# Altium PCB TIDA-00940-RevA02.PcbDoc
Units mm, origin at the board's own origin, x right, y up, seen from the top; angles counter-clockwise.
Board outline 125.73 x 87.63 mm, 2 copper layers (Top Layer, Bottom Layer), stack 1.575 mm thick; 42 components, 20 nets, 88 pads, 5 vias.
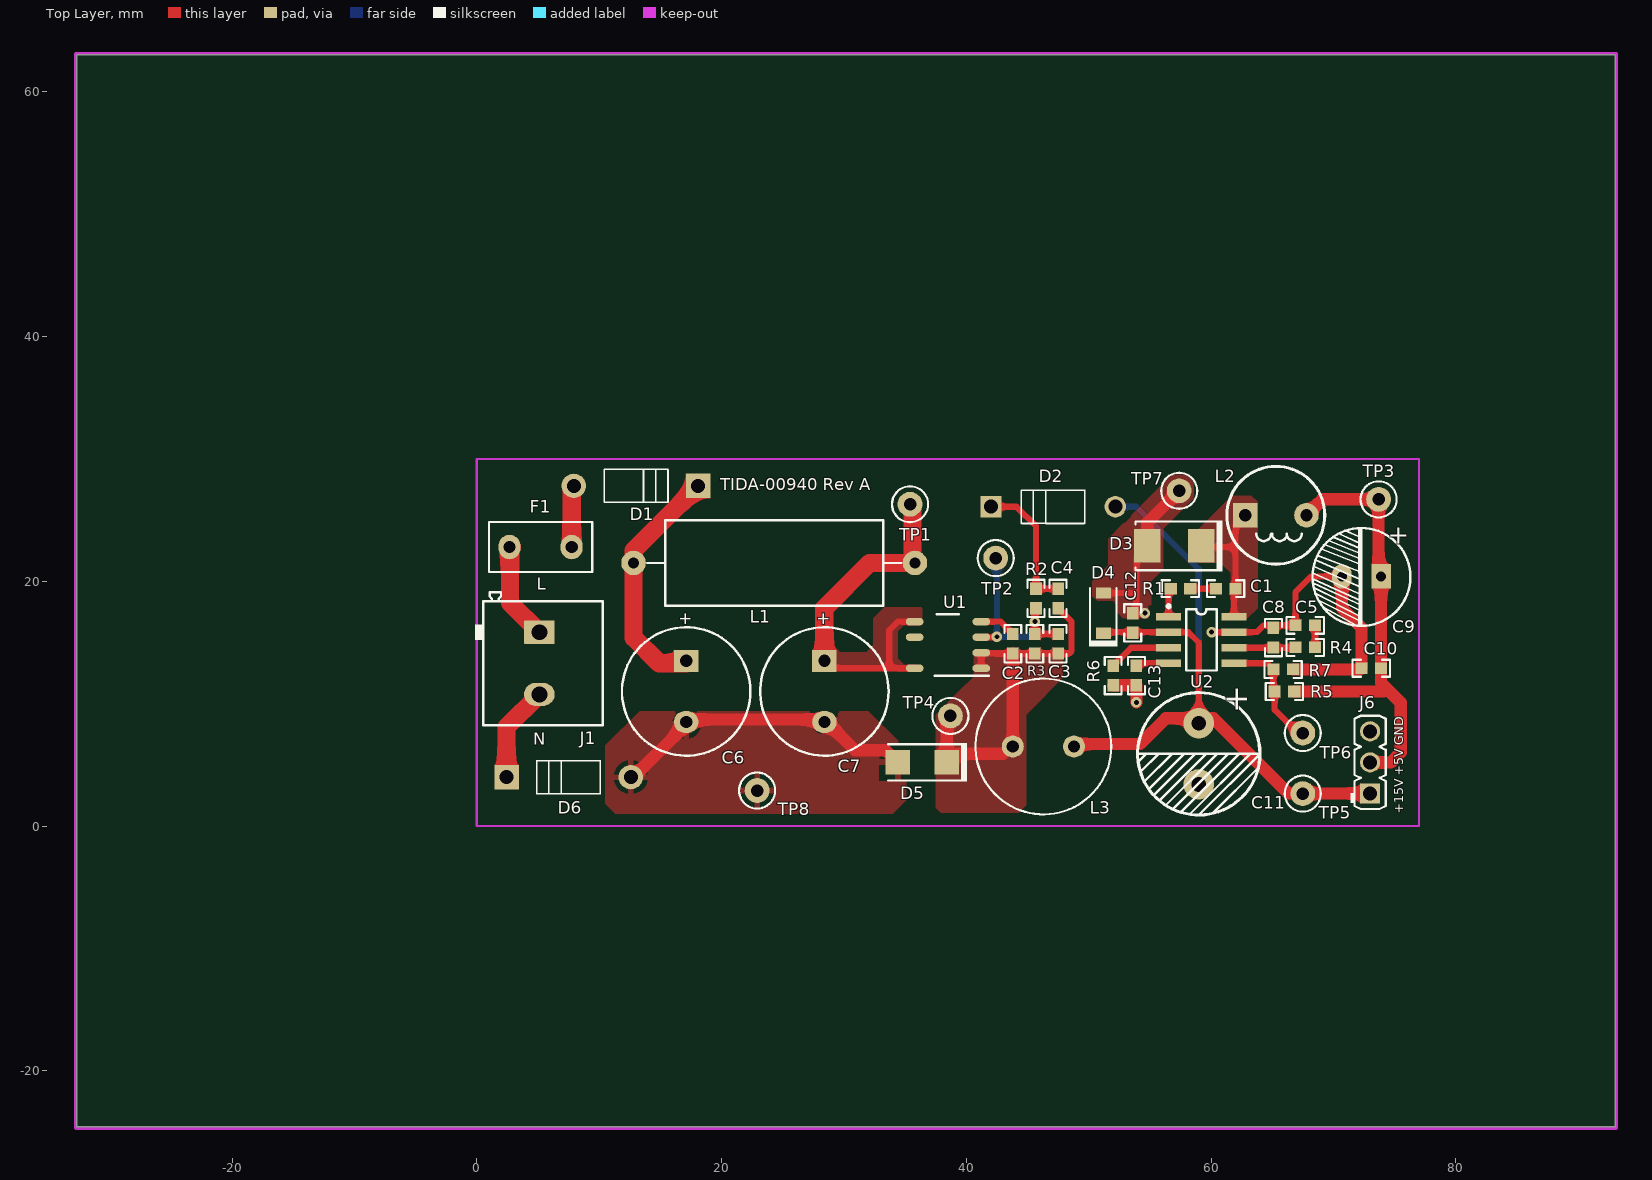
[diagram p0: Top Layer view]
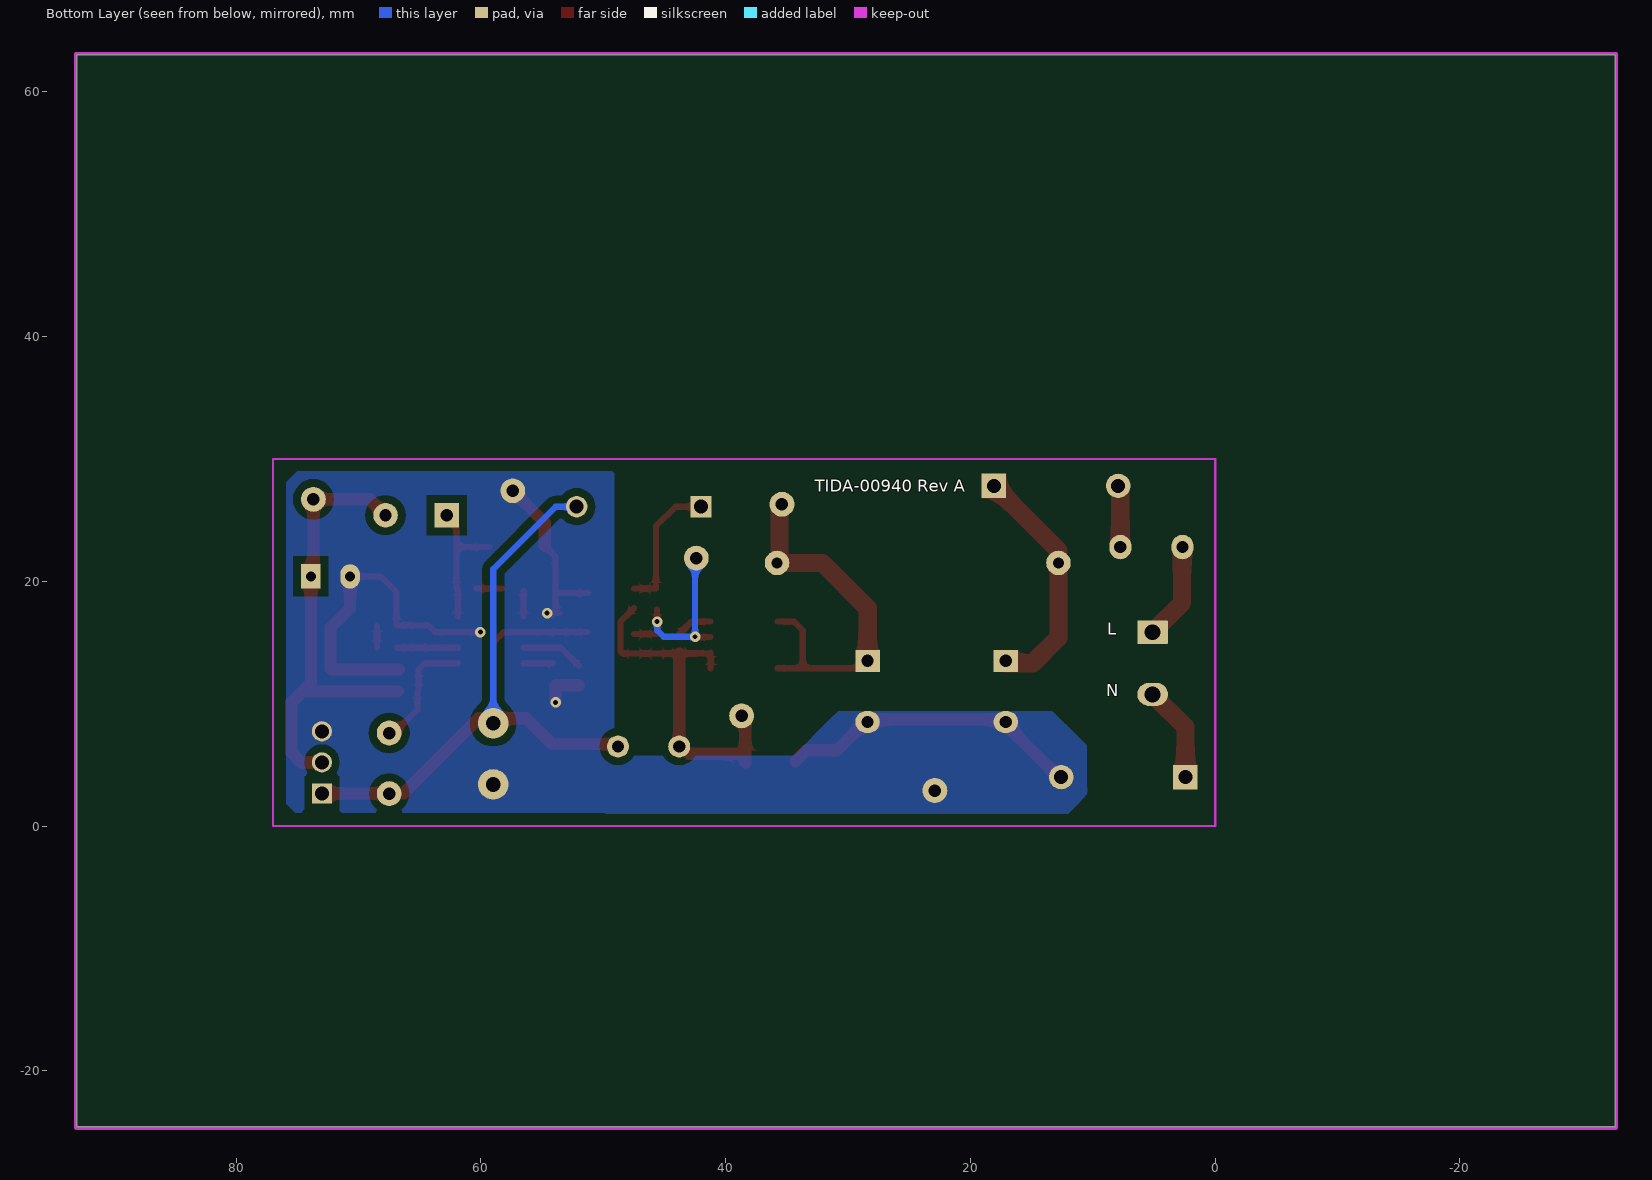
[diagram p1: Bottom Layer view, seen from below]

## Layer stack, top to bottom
Top Solder: solder mask 0.0102, Solder Resist, Dk 3.5
Top Layer: signal copper 0.0356
Dielectric1: core 1.5037, FR-4, Dk 4.8
Bottom Layer: signal copper 0.0356
Bottom Solder: solder mask 0.0102, Solder Resist, Dk 3.5

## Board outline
-32.7,-24.6 93.03,-24.6 93.03,63.03 -32.7,63.03

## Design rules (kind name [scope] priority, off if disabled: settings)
AcuteAngle [All] p1: minimum=4.50000000000000E+0001 checktracksonly=FALSE
AssemblyTestPointUsage [All] p1: valid=2
Clearance Clearance_Keepouts [((IsTrack Or IsArc) And Not InPoly) And IsFree and IsKeepOut vs ((IsTrack Or IsArc) And Not InPoly) And IsFree and IsKeepOut] p1 off: gap=0
Clearance Clearance_BoardEdge_MountingHoles [OnCopper and InComponentClass('Mounting Holes') vs IsKeepOut] p2 off: gap=1.016
Clearance Clearance_BoardEdge_Poly [OnCopper and InPoly vs IsKeepOut] p3 off: gap=0.635
Clearance Clearance_BoardEdge [OnCopper and Not InComponentClass('Logo') and not InComponentClass('FiducialMark') and not InRegion(1000,500,4000,800) and Not IsKeepout vs IsKeepOut] p4 off: gap=1.905
Clearance Clearance_Poly [InPolygon] p5: gap=0.635
Clearance [All] p6: gap=0.2
ComponentClearance ComponentClearance_MountingHoles_FiducialMarks [InComponentClass('Mounting Holes') vs InComponentClass('FiducialMark')] p1 off: gap=1.27 collisioncheckmode=3 verticalgap=0.254 showdistances=FALSE
ComponentClearance ComponentClearance_Shunt [InComponentClass('Header') vs InComponentClass('Shunt')] p2 off: gap=0 collisioncheckmode=3 verticalgap=0 showdistances=FALSE
ComponentClearance ComponentClearance_Logo [InComponentClass('Logo')] p3 off: gap=1.27 collisioncheckmode=3 verticalgap=0.254 showdistances=FALSE
ComponentClearance ComponentClearance_ScrewToNut [(HasFootprint('NY PMS 440 0025 PH')) vs (HasFootprint('Keystone_1902C'))] p4 off: gap=0.127 collisioncheckmode=3 verticalgap=0.254 showdistances=FALSE
ComponentClearance ComponentClearance_MountingHoles [InComponentClass('Mounting Holes')] p5 off: gap=6.35 collisioncheckmode=3 verticalgap=2540 showdistances=FALSE
ComponentClearance ComponentClearance_SmallPassives [HasFootprint('0201*') or HasFootprint('0402*') or HasFootprint('0508') or HasFootprint('0603*') or HasFootprint('0612') or HasFootprint('0805*') or HasFootprint('0815*') or HasFootprint('0830*') or HasFootprint('1206*') or HasFootprint('1210*') or HasFootprint('1808*') or HasFootprint('1812*') or HasFootprint('1825*') or HasFootprint('2010*') or HasFootprint('2220*') or HasFootprint('2225*') or HasFootprint('2512*') or HasFootprint('2728*') or HasFootprint('3518*') vs HasFootprint('0201*') or HasFootprint('0402*') or HasFootprint('0508') or HasFootprint('0603*') or HasFootprint('0612') or HasFootprint('0805*') or HasFootprint('0815*') or HasFootprint('0830*') or HasFootprint('1206*') or HasFootprint('1210*') or HasFootprint('1808*') or HasFootprint('1812*') or HasFootprint('1825*') or HasFootprint('2010*') or HasFootprint('2220*') or HasFootprint('2225*') or HasFootprint('2512*') or HasFootprint('2728*') or HasFootprint('3518*')] p6 off: gap=0.508 collisioncheckmode=3 verticalgap=0.254 showdistances=FALSE
ComponentClearance ComponentClearance_THtoSMT [IsThruComponent vs IsSMTComponent] p7 off: gap=2.54 collisioncheckmode=3 verticalgap=0.762 showdistances=FALSE
ComponentClearance ComponentClearance_THtoTH [IsThruComponent vs IsThruComponent] p8 off: gap=3 collisioncheckmode=3 verticalgap=0.762 showdistances=FALSE
ComponentClearance [All] p9 off: gap=1.016 collisioncheckmode=3 verticalgap=0.254 showdistances=FALSE
DiffPairsRouting [All] p1: maxlimit=2.54 minlimit=0.254 mostfreqgap=0.254 toplayer_minwidth=0.381 toplayer_maxwidth=0.381 toplayer_prefwidth=0.381 bottomlayer_minwidth=0.381 bottomlayer_maxwidth=0.381 bottomlayer_prefwidth=0.381 maxuncoupledlength=25.4
FabricationTestPointUsage TestPointUsage [All] p1: valid=2 allowmultiple=FALSE
FabricationTestpoint Testpoint [All] p1: side=3 testpointundercomponent=TRUE minsize=1.016 maxsize=2.54 preferedsize=1.524 minholesize=0 maxholesize=1.016 preferedholesize=0.813 testpointgrid=0.025 allowsidetop=TRUE allowsidebottom=TRUE usegrid=TRUE gridtolerance=0
FanoutControl Fanout_LCC [IsLCC] p1: bgadir=Out bgaviamode=Centered fanoutstyle=Auto fanoutdirection=Alternating viagrid=0.025 // Fanout_LCC (Default Rule)
FanoutControl Fanout_BGA [IsBGA] p2: bgadir=Out bgaviamode=Centered fanoutstyle=Auto fanoutdirection=Alternating viagrid=0.025 // Fanout_BGA (Default Rule)
FanoutControl Fanout_Default [All] p4: bgadir=Out bgaviamode=Centered fanoutstyle=Auto fanoutdirection=Alternating viagrid=0.025 // Fanout_Default (Default Rule)
FanoutControl Fanout_Small [(CompPinCount < 5)] p5: bgadir=Out bgaviamode=Centered fanoutstyle=Auto fanoutdirection=OutThenIn viagrid=0.025 // Fanout_Small (Default Rule)
HoleSize [All] p1: absolutevalues=TRUE maxlimit=6.375 minlimit=0.203 maxpercent=80.000 minpercent=20.000
MinimumAnnularRing MinimumAnnularRing_ThermalPadVias [IsVia and InAnyComponent] p1: minimumring=0.15
MinimumAnnularRing [All] p2: minimumring=0.229
MinimumSolderMaskSliver MinimumSolderMaskSliver_Logo [InComponentClass('Logo') vs InComponentClass('Logo')] p1: minsoldermaskwidth=0.018
MinimumSolderMaskSliver [All] p2: minsoldermaskwidth=0.1
PlaneConnect [All] p1: planeconnectstyle=Relief reliefexpansion=0.254 reliefentries=4 reliefconductorwidth=0.254 reliefairgap=0.254
PolygonConnect [All] p1: connectstyle=Direct reliefconductorwidth=0.5 reliefentries=4 polygonreliefangle="90 Angle" airgapwidth=0.5
RoomDefinition TIDA-00940-RevA01 [InComponentClass('TIDA-00940-RevA01')] p1: confinementstyle=ConfineIn formatcopy=TRUE lockcomponents=FALSE outline -50.277,-63.564 0.523,-63.564 0.523,-38.164 -50.277,-38.164
RoutingVias ThermalPadVias [IsVia and InAnyComponent] p1: holewidth=0.2 width=0.5 viastyle="Through Hole" minholewidth=0.2 minwidth=0.5 maxholewidth=0.33 maxwidth=0.6
RoutingVias [All] p2: holewidth=0.406 width=0.864 viastyle="Through Hole" minholewidth=0.2 minwidth=0.66 maxholewidth=1.016 maxwidth=1.651
SilkToBoardRegionClearance [Not ((IsComment or IsDesignator) And (Hide <> 'False')) and not InRegion(1000,500,4000,800)] p1:
SilkToSilkClearance SilkToSilkClearance_Pb-FreeLogo [(HasFootprint('Pb-Free_Overlay_Medium') OR HasFootprint('Pb-Free_Overlay_Small')) vs (HasFootprint('Pb-Free_Overlay_Medium') OR HasFootprint('Pb-Free_Overlay_Small'))] p1: silktosilkclearance=0
SilkToSilkClearance [All] p2: silktosilkclearance=0.102
SilkToSolderMaskClearance SilkToComonentPadClearance [IsPad and InAnycomponent] p1: minsilkscreentomaskgap=0.127 clearancetoexposedcopper=TRUE
SilkToSolderMaskClearance "Silk to Solder Mask Opening" [All] p2: minsilkscreentomaskgap=0.102 clearancetoexposedcopper=FALSE
SolderMaskExpansion [All] p1: expansion=0.05
UnpouredPolygon [All] p1: allowunpoured=FALSE
Width [All] p1: maxlimit=2.54 minlimit=0.152 preferedwidth=0.254 checkconnectedcopper=TRUE
14 further rules are at their usual default settings.

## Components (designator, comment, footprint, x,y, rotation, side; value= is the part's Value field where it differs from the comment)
C1 "C1608X7R1H104K080AA" 0603 61.2,19.4 r0 top
C2 "C1608X7R1H104K080AA" 0603 43.8,14.9 r270 top
C3 "C1608X7R1H103K" 0603 47.5,14.9 r270 top
C4 "C1608X7R1H153K080AA" 0603 47.5,18.6 r270 top
C5 "06031C222JAT2A" 0603 67.7,16.4 r0 top
C6 "UCY2G100MPD1TD" CY_1000x1600 17.1,11 r270 top
C7 "UCY2G100MPD1TD" CY_1000x1600 28.4,11 r270 top
C8 "06035A101FAT2A" 0603 65.1,15.4 r270 top
C9 "UPW1A471MPD" E/P3.2/D8 72.3,20.4 r180 top
C10 "C1608X7R1H103K" 0603 73.1,12.9 r180 top
C11 "UPW1E331MPD" E5/10 59,5.9 r270 top
C12 "C1608X7R1H103K" 0603 53.6,16.6 r90 top
C13 "C1608X7R1H103K" 0603 53.9,12.3 r270 top
D1 "1N4007" DO-41#1 13,27.8 r180 top
D2 "1N4007" DO-41#2 47.1,26.1 r0 top
D3 "B240-13-F" SMB 57,22.9 r180 top
D4 "MMSZ4705T1G" SOD-123 51.2,17.4 r90 top
D5 "US1M-13-F" SMA 36.4,5.2 r180 top
D6 "1N4007" DO-41#1 7.5,4 r0 top
F1 "RST 500" Fuse_RST 5.2,22.8 r180 top
J1 "1715721" PhoenixContact_1715721 5.1,13.3 r270 top
J6 "61300311121" WURTH_61300311121 73,5.2 r90 top
L1 "5800-102-RC" 5800 24.3,21.5 r0 top
L2 "7447471102" Inductor-P5D8 65.3,25.4 r90 top
L3 "7447471102" WE-TIS-1111 46.3,6.5 r0 top
R1 "CRCW06030000Z0EA" 0603 57.5,19.4 r0 top
R2 "RT0603DRE07135KL" 0603 45.7,18.6 r90 top
R3 "RC0603FR-0710KL" 0603 45.6,14.9 r90 top
R4 "CRCW060347K0JNEA" 0603 67.7,14.6 r0 top
R5 "RC0603FR-0751RL" 0603 66,11 r0 top
R6 "CRCW0603100KFKEA" 0603 52,12.3 r90 top
R7 "CRCW06033K90JNEA" 0603 65.9,12.8 r180 top
TP1 "5000" Keystone5000 35.4,26.3 r0 top
TP2 "5000" Keystone5000 42.4,21.9 r0 top
TP3 "5000" Keystone5000 73.7,26.7 r0 top
TP4 "5000" Keystone5000 38.7,9 r0 top
TP5 "5000" Keystone5000 67.501,2.647 r0 top
TP6 "5000" Keystone5000 67.5,7.6 r0 top
TP7 "5001" Keystone5001 57.4,27.4 r0 top
TP8 "5001" Keystone5001 22.9,2.9 r0 top
U1 "UCC28881DR" D0007A_N 38.5,14.8 r180 top
U2 "TPS5405" SO-G8/E2.5 59.2,15.2 r270 top

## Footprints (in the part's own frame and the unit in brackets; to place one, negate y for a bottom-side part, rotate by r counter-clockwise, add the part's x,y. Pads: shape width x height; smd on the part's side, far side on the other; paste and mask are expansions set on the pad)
0603 [mm] "0603 from SM-752 data"
  rect 1x0.95 smd: 1(-0.8,0) 2(0.8,0)
  silkscreen extent -1.52,-0.69 1.52,0.69, body extent -0.87,-0.47 0.87,0.47, height 1
5800 [mm] "BOURNS"
  round 2 hole 0.9: 1(-11.5,0) 2(11.5,0)
  silkscreen extent -10.4,-3.5 10.4,3.5, body extent -11.81,-3.5 11.82,3.48, height 6.96
CY_1000x1600 [mm] "TH, 2-Leads, Dia 10mm, Pitch 5mm"
  rect 1.8x2 hole 1: 1(-2.5,0)
  oval 1.8x2 hole 1: 2(2.5,0)
  silkscreen extent -5.25,-5.25 5.25,5.25, body extent -5.2,-5.23 5.25,5.25, height 17.5
D0007A_N [mm] "SOIC, 7-Leads, Body 4.9x3.9mm, Pitch 1.27mm, IPC Medium Density"
  oval 1.45x0.6 smd: 1(-2.725,1.905) 2(-2.725,0.635) 3(-2.725,-0.635) 4(-2.725,-1.905) 5(2.725,-1.905) 6(2.725,-0.635) 8(2.725,1.905)
  silkscreen extent -3.32,-2.5 1.1,2.52, body extent -3.01,-2.45 3.01,2.45, height 1.75
DO-41#1 [mm] "diode"
  rect 2x2 hole 1.15: 1(-5.08,0)
  round 2 hole 1.15: 2(5.08,0)
  silkscreen extent -2.62,-1.37 2.59,1.35, body extent -5.51,-1.36 5.51,1.36, height 2.72
DO-41#2 [mm] "diode"
  rect 1.75x1.75 hole 1.15: 1(-5.08,0)
  round 1.75 hole 1.15: 2(5.08,0)
  silkscreen extent -2.62,-1.37 2.59,1.35, body extent -5.51,-1.36 5.51,1.36, height 2.72
E5/10 [mm]
  round 2.5 hole 1.2: 1(-2.5,0) 2(2.5,0)
  silkscreen extent -5,-5 5,5
E/P3.2/D8 [mm]
  rect 1.6x2 hole 0.8: 1(-1.6,0)
  oval 1.6x2 hole 0.8: 2(1.6,0)
  silkscreen extent -4,-3.96 4,4.04
Fuse_RST [mm] "Bel Fuse RST series May2012D"
  oval 1.8x2 hole 1: 1(-2.54,0) 2(2.54,0)
  silkscreen extent -4.23,-2.05 4.23,2.05, body extent -4.22,-2.05 4.23,2.05, height 7.9
Inductor-P5D8 [mm]
  rect 2x2 hole 1: 1(0,2.5)
  round 2 hole 1: 2(0,-2.5)
  silkscreen extent -4,-4 4,4
Keystone5000 [mil] "For Keystone 500x miniature loop terminals"
  round 80 hole 40: 1(0,0)
  silkscreen extent -58,-58 58,58, body extent -49,-49 49,49, height 182
Keystone5001 [mil] "For Keystone 500x miniature loop terminals"
  round 80 hole 40: 1(0,0)
  silkscreen extent -58,-58 58,58, body extent -49,-49 49,49, height 182
PhoenixContact_1715721 [mm] "Phoenix Contact 1715721 used on LM3445 design from Longmont"
  rrect5% 1.9x2.5 hole 1.3: 1(-2.54,0)
  oval 1.9x2.5 hole 1.3: 2(2.54,0)
  silkscreen extent -5.82,-5.25 5.08,5.2, body extent -5.82,-4.6 5.08,5.2, height 14.2
SMA [mm] "Molded Diode, 2-Leads, Body 4.3x2.6mm, IPC Medium Density, based on OnSemi component dimensions and land pattern"
  rect 2x2 smd: 1(-2,0) 2(2,0)
  silkscreen extent -3.66,-1.57 2.79,1.57, body extent -2.6,-1.3 2.6,1.3, height 2.42
SMB [mm] "Molded Diode, 2-Leads, Body 5.4x3.6mm, IPC Medium Density, based on OnSemi component dimensions"
  rect 2.159x2.743 smd: 1(-2.21,0) 2(2.21,0)
  silkscreen extent -3.94,-2.08 3.18,2.08, body extent -2.7,-1.8 2.7,1.8, height 2.32
SO-G8/E2.5 [mm]
  rect 0.6x2.05 smd: 1(-1.915,-2.666) 2(-0.645,-2.666) 3(0.625,-2.666) 4(1.895,-2.666) 5(1.895,2.684) 6(0.625,2.684) 7(-0.645,2.684) 8(-1.915,2.684)
  silkscreen extent -2.89,-2.79 2.49,1.26
SOD-123 [mm] "On Semi recommended land pattern"
  rect 0.915x1.22 smd: 1(-1.637,0) 2(1.637,0)
  silkscreen extent -2.74,-1.17 2.03,1.17, body extent -1.93,-0.9 1.93,0.9, height 1.35
WE-TIS-1111 [mm] "WURTH"
  round 1.8 hole 1.016: 1(-2.5,0) 2(2.5,0)
  silkscreen extent -5.55,-5.55 5.55,5.55, body extent -5.51,-5.51 5.51,5.51, height 11.5
WURTH_61300311121 [mm] "Header, 2.54mm, 3x1, TH"
  rect 1.65x1.65 hole 1.15: 1(-2.54,0)
  round 1.65 hole 1.15: 2(0,0) 3(2.54,0)
  silkscreen extent -3.81,-1.27 3.81,1.6, body extent -3.81,-1.27 3.81,1.27, height 8.54

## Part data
C1 C2: "CAP, CERM, 0.1 µF, 50 V, +/- 10%, X7R, 0603"
C3 C10 C12 C13: "CAP, CERM, 0.01 µF, 50 V, +/- 10%, X7R, 0603"
C4: "CAP, CERM, 0.015 µF, 50 V, +/- 10%, X7R, AEC-Q200 Grade 1, 0603"
C5: "CAP, CERM, 2200 pF, 100 V, +/- 5%, X7R, 0603"
C6 C7: "CAP, AL, 10 µF, 400 V, +/- 20%,  ohm, TH"
C8: "CAP, CERM, 100 pF, 50 V, +/- 1%, C0G/NP0, 0603"
C9: library part UVR1V100MDD1TA, "CAP, AL, 10 µF, 35 V, +/- 20%, TH"
C11: library part UVR1V100MDD1TA, "CAP, AL, 330 µF, 25 V, +/- 20%, TH"
D1 D2 D6: "Diode, P-N, 1000 V, 1 A, TH"
D3: "Diode, Schottky, 40 V, 2 A, SMB"
D4: "Diode, Zener, 18 V, 500 mW, SOD-123"
D5: "Diode, Ultrafast, 1000 V, 1 A, SMA"
F1: "Fuse, 0.5 A, 250VAC/VDC, TH"
J1: "Conn Term Block, 2POS, 5.08mm, TH"
J6: "Header, 2.54 mm, 3x1, Gold, TH"
L1: "Inductor, Wirewound, Ferrite, 1 mH, 0.2 A, 2.3 ohm, TH"
L2: "Inductor, Wirewound, Ferrite, 82uH, 1.1 A, 1.2 ohm, TH"
L3: "Inductor, Wirewound, Ferrite, 1 mH, 0.4 A, 1.2 ohm, TH"
R1: "RES, 0, 5%, 0.1 W, 0603"
R2: "RES, 135 k, 0.5%, 0.1 W, 0603"
R3: "RES, 10.0 k, 1%, 0.1 W, 0603"
R4: "RES, 47 k, 5%, 0.1 W, 0603"
R5: "RES, 51.0, 1%, 0.1 W, 0603"
R6: "RES, 100 k, 1%, 0.1 W, 0603"
R7: "RES, 3.9 k, 5%, 0.1 W, 0603"
TP1 TP2 TP3 TP4 TP5 TP6: "Test Point, Miniature, Red, TH"
TP7 TP8: "Test Point, Miniature, Black, TH"
U1: "700-V Lowest Quiescent Current Off-Line Switcher, D0007A"

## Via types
v1: diameter 0.864, hole 0.406, Top Layer to Bottom Layer, 5 vias

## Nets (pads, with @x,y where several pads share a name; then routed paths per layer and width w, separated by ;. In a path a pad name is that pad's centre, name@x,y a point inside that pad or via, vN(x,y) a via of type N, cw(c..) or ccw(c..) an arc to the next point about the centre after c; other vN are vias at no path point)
+5V: C9.1 C10.1 J6.2 L2.2 R5.2 TP3.1 | length 37.8
  Top Layer w1: R5.2 74.1,11 74.35,11.25 ; L2.2 69.1,26.7 TP3.1 C9.1@73.7,20.6 ; J6.2 74.7,5.2 75.5,6 75.5,10.1 74.35,11.25 ; C10.1 73.9,11.7 74.35,11.25 ; C10.1@73.9,13.2 C9.1
+15V: C11.1 C12.1 D2.2 D4.1 J6.1 L3.2 TP5.1 U2.2 | length 63.4
  Top Layer w0.5: D4.1@51.282,15.845 U2.2 58.155,15.845 59,15 C11.1@59,8.8
  Top Layer w1: L3.2@48.8,6.7 54.2,6.7 56.3,8.8 59,8.8 60.2,8.8 66.34,2.66 J6.1
  Bottom Layer w0.5: D2.2 53.9,26.1 59,21 C11.1
GND: C5.1 C6.2 C7.2 C8.1 C9.2 C10.2 C11.2 C12.2 C13.2 D3.2 D4.2 D5.2 D6.2 J6.3 R6.1 R7.1 TP7.1 TP8.1 U2.7 | length 70.6
  Top Layer w0.5: D4.2 53.862,19.038 53.9,19 ; C12.2 v1(54.6,17.4) ; C12.2@53.9,17.4 53.9,19 ; D3.2 53.9,22.01 53.9,19 ; v1(60.045,15.855) 60.045,15.845 U2.7 63.745,15.845 64.3,16.4 C5.1 66.9,19.1 68.2,20.4 C9.2
  Top Layer w1: D6.2@12.8,4 C6.2@17.1,8.3 ; C6.2@17.5,8.7 28.4,8.7 30.9,6.2 33.4,6.2 D5.2@34.3,5.3 ; R6.1 C13.2 v1(53.9,10.1) ; D3.2 54.79,24.79 TP7.1 ; R7.1 C10.2@72.2,12.8 ; C9.2 70.7,17.8 72.3,16.2 C10.2
NetC1_1: C1.1 R1.2 | length 2.1
  Top Layer w0.5: R1.2 C1.1
NetC1_2: C1.2 D3.1 L2.1 U2.8 | length 11.2
  Top Layer w0.5: D3.1@59.31,22.8 62,22.8 ; U2.8 C1.2@61.884,19.284 ; C1.2 62,22.8 ; L2.1 62,24.6 62,22.8
NetC2_1: C2.1 U1.4 | length 3
  Top Layer w0.5: U1.4 42.795,16.705 C2.1
NetC2_2: C2.2 C3.2 C4.2 D5.1 L3.1 R3.1 TP4.1 U1.1 U1.2 | length 29
  Top Layer w0.5: U1.1 U1.2 ; U1.2@41.29,14.1 R3.1 C3.2 48.4,14.1 48.6,14.3 48.6,16.7 C4.2
  Top Layer w1: D5.1 TP4.1@38.4,8.7 ; D5.1@38.75,5.75 38.9,5.9 43,5.9 43.8,6.7 C2.2
NetC3_1: C3.1 R2.1 R3.2 TP2.1 U1.3 | length 15.5
  Top Layer w0.5: U1.3 42.465,15.435 v1(42.5,15.47) ; R2.1@45.6,17.7 v1(45.6,16.7) R3.2 C3.1
  Bottom Layer w0.5: TP2.1@42.5,21.8 v1(42.5,15.47) 45.07,15.47 45.6,16 v1(45.6,16.7)
NetC4_1: C4.1 D2.1 R2.2 | length 11.2
  Top Layer w0.5: D2.1 44.1,26.1 45.7,24.5 R2.2 C4.1
NetC5_2: C5.2 R4.2 | length 1.8
  Top Layer w0.5: R4.2 C5.2
NetC6_1: C6.1 D1.1 L1.1 | length 19.7
  Top Layer w1: L1.1@12.7,21.4 L1.1@12.8,21.3
  Top Layer w1.5: L1.1@12.8,21.3 12.8,15.4 14.9,13.3 C6.1@17.1,13.3 ; L1.1 12.8,22.52 D1.1
NetC7_1: C7.1 L1.2 TP1.1 U1.5 U1.8 | length 30.6
  Top Layer w0.5: C7.1@28.4,13.7 29.205,12.895 33.7,12.895 ; U1.8 33.7,12.895 ; U1.5 34.405,16.705 33.7,16 33.7,12.895
  Top Layer w1.5: C7.1@28.4,13.7 28.4,17.8 32.1,21.5 35.6,21.5 TP1.1@35.6,26.1
NetC8_2: C8.2 R4.1 U2.6 | length 5
  Top Layer w0.5: U2.6 R4.1@66.875,14.575
NetC13_1: C13.1 U2.4 | length 2.4
  Top Layer w0.5: C13.1@54.105,13.305 U2.4
NetD1_2: D1.2 F1.1 | length 4.7
  Top Layer w1.5: F1.1 D1.2@7.74,27.48
NetD6_1: D6.1 J1.2 | length 7.9
  Top Layer w1.5: D6.1 2.42,8.08 J1.2
NetF1_2: F1.2 J1.1 | length 8
  Top Layer w1.5: F1.2@2.86,22.8 2.7,22.64 2.7,18.24 J1.1
NetR1_1: R1.1 U2.1 | length 2.1
  Top Layer w0.5: U2.1 R1.1@56.534,19.234
NetR5_1: R5.1 R7.2 TP6.1 U2.5 | length 9.3
  Top Layer w0.5: U2.5 64.595,13.305 R7.2 R5.1@65.1,11.1 ; R5.1 65.2,9.5 TP6.1@67.1,7.6
NetR6_2: R6.2 U2.3 | length 5.1
  Top Layer w0.5: R6.2 53.475,14.575 U2.3
pads on no net: U1.6

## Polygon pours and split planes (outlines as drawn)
GND on Top Layer "Top Layer-No Net" (solid, remove dead copper, pour order 2): 35.1,6.3 32,9.4 24.8,9.4 13.3,9.4 10.5,6.6 10.5,1.8 11.3,1 15.3,1 34,1 35.1,2.1
NetC7_1 on Top Layer "Top Layer-No Net 2" (solid, remove dead copper, pour order 8): 28.9,14.9 29,14.9 29.7,14.2 31.8,14.2 32.4,14.8 32.4,16.1 32.4,17 32.8,17.4 33.3,17.9 35.7,17.9 36.3,17.9 36.4,17.8 36.4,16.7 36.4,16.5 36.3,16.4 34.9,16.4 34.4,15.9 34.4,13.7 34.8,13.3 34.9,13.2 35.9,13.2 36,13.2 36.1,13.1 36.2,13 36.2,12.6 34.4,12.6 34.3,12.7 29.1,12.7
NetC1_2 on Top Layer "Top Layer-No Net 3" (solid, remove dead copper, pour order 10): 58.7,24 61.7,27 63.3,27 63.8,26.5 63.8,24.9 63.8,17.8 62.9,16.9 62.8,17 61.6,17 61.6,20.7 61.1,21.2 60.8,21.5 59,21.5
NetC2_2 on Top Layer "Top Layer-No Net 4" (solid, remove dead copper, pour order 12): 41.2,14.378 47.822,14.378 47.9,14.3 47.9,12.1 45.2,9.4 44.9,9.1 44.9,6.7 44.9,1.7 44.3,1.1 37.9,1.1 37.5,1.5 37.5,9.1 39.4,11 40.6,12.2 40.6,14.3
GND on Top Layer "Top Layer-No Net 5" (solid, remove dead copper, pour order 14): 54.6,17 52.8,17 52.4,17.4 52.3,17.5 52.3,18.1 52,18.4 50.7,18.4 50.3,18.8 50.3,18.9 50.3,20 50.8,20.5 51.6,21.3 51.6,23.5 56.8,28.7 58,28.7 58.6,28.1 58.6,27.2 58.6,26.8 56.9,25.1 56.1,24.3 56.1,21.8 56.1,21 55.3,20.2 55.1,20 55.1,17.6 55.1,17.2 54.9,17
GND on Bottom Layer "Top Layer-No Net 1" (solid, remove dead copper, pour order 4): 49.1,29 49.1,1.7 49.7,1.1 75.2,1.1 75.9,1.8 75.9,28.1 75,29
GND on Bottom Layer "Bottom Layer-No Net" (solid, remove dead copper, pour order 6): 40.75,5.75 38.75,5.75 34.45,5.75 31.4,8.8 30.8,9.4 23.1,9.4 13.3,9.4 11.2,7.3 10.5,6.6 10.5,4.693 10.496,3.455 10.464,2.877 10.504,2.592 11.2,1.8 12,1 49.8,1 50.1,1.3 50.1,5.75

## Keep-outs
Keep-Out Layer:
  lines w0.2: 0,0 0,30 77,30 77,0 0,0
  lines w0.254: -32.827,-24.6 ccw(c-32.7,-24.6) -32.7,-24.727 ; -32.827,-24.6 ccw(c-32.7,-24.6) -32.7,-24.727 ; -32.827,-24.6 -32.827,63.03 ; -32.827,63.03 cw(c-32.7,63.03) -32.7,63.157 ; -32.827,63.03 cw(c-32.7,63.03) -32.7,63.157 ; -32.7,-24.727 93.03,-24.727 ; -32.7,63.157 93.03,63.157 ; 93.03,-24.727 ccw(c93.03,-24.6) 93.157,-24.6 ; 93.03,-24.727 ccw(c93.03,-24.6) 93.157,-24.6 ; 93.03,63.157 cw(c93.03,63.03) 93.157,63.03 ; 93.03,63.157 cw(c93.03,63.03) 93.157,63.03 ; 93.157,-24.6 93.157,63.03
  text ".Layer_Name" at -18.044,-46.406 h1.52

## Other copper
Top Layer:
  text ".Layer_Name" at -18.044,-46.406 h1.52
Bottom Layer:
  text ".Layer_Name" at -18.044,-46.406 h1.52

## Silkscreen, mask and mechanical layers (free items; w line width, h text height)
Top Overlay:
  text "TIDA-00940 Rev A" at 19.9,27.1 h1.7
  text "L" at 4.9,19 h1.7
  text "GND" at 76,6.6 h1.3 r90
  text "N" at 4.6,6.3 h1.7
  text "+5V" at 76,4.1 h1.3 r90
  text "+15V" at 76,1 h1.3 r90
  text ".Layer_Name" at -18.044,-46.406 h1.52
Bottom Overlay:
  text "TIDA-00940 Rev A" at 32.7,27 h1.7
  text "L" at 8.8,15.3 h1.7
  text "N" at 8.9,10.3 h1.7
  text ".Layer_Name" at -18.044,-46.406 h1.52
Top Paste:
  text ".Layer_Name" at -18.044,-46.406 h1.52
Bottom Paste:
  text ".Layer_Name" at -18.044,-46.406 h1.52
Top Solder:
  text ".Layer_Name" at -18.044,-46.406 h1.52
  text ".Layer_Name" at -18.044,-46.406 h1.52
Bottom Solder:
  text ".Layer_Name" at -18.044,-46.406 h1.52
Drill Guide:
  text ".Layer_Name" at -18.044,-46.406 h1.52
M1 Board Outline:
  lines w0.254: -32.7,-24.6 -32.7,63.03 93.03,63.03 93.03,-24.6 -32.7,-24.6
  lines w3: 1.9,13.3 7.8,13.3 ; 10.2,19.6 10.2,25.5 ; 15.4,11 35.3,11 37,11 38.5,12.5 38.5,13.9 ; 38.5,13.6 38.5,27.8
  text ".Layer_Name" at -18.044,-46.406 h1.52
M2 Board Dimensions:
  rectangle: -32.7,-31.585 -29.525,-28.41
  rectangle: -29.525,-34.76 -20,-31.585
  lines w0.178: -32.7,-31.585 -7.3,-31.585 ; -29.525,-34.76 -29.525,-28.41 ; -26.35,-34.76 -26.35,-28.41 ; -20,-34.76 -20,-28.41 ; -13.65,-34.76 -13.65,-28.41 ; -32.7,-34.76 -7.3,-34.76 -7.3,-28.41 -32.7,-28.41 -32.7,-34.76
  text ".Layer_Name" at -18.044,-46.406 h1.52
M3 3D STEP Top:
  text ".Layer_Name" at -18.044,-46.406 h1.52
M4 3D STEP Bottom:
  text ".Layer_Name" at -18.044,-46.406 h1.52
M5 Assembly Top:
  lines w0.254: -40.117,-48.226 127.523,-48.226 ; -40.117,-43.062 127.574,-43.062 ; -40.117,-37.897 -40.117,-53.391 61.61,-53.391 127.574,-53.391 127.574,-37.897 -40.104,-37.897 -40.104,-53.391 -0.086,-53.391 ; 22.494,-53.391 22.494,-37.897 ; 54.676,-43.062 54.676,-37.897 ; 76.012,-43.062 76.012,-37.897 ; 91.811,-53.556 91.811,-48.404
  text "COMPONENTS MARKED 'DNP' SHOULD NOT BE POPULATED." at -3.401,-32.69 h1.52
  text "ASSEMBLY VARIANT:" at -3.414,-35.624 h1.52
  text ".VariantName" at 22.901,-35.624 h1.52
  text "PCB VIEWED FROM TOP SIDE" at -38.504,-41.254 h1.52
  text "BOARD #:" at 24.399,-41.254 h1.52
  text ".PRJ_Number" at 38.255,-41.254 h1.52
  text "REV:" at 59.705,-41.254 h1.52
  text ".PCB_Rev" at 67.109,-41.254 h1.52
  text "SVN REV:" at 80.99,-41.254 h1.52
  text ".VersionControl_RevNumber" at 93.843,-41.254 h1.52
  text "TID #:" at 24.399,-46.419 h1.52
  text ".TID" at 38.255,-46.419 h1.52
  text "PLOT NAME =" at -38.504,-51.634 h1.52
  text ".plot_File_Name" at -18.044,-51.634 h1.52
  text "GENERATED    :" at 24.45,-51.634 h1.52
  text ".Print_Date" at 46.535,-51.634 h1.52
  text ".Print_Time" at 65.052,-51.634 h1.52
  text "TEXAS INSTRUMENTS" at 97.17,-51.634 h1.52
M6 Assembly Bottom:
  lines w0.254: -40.13,-43.074 127.561,-43.074 ; -40.079,-48.239 127.561,-48.239 ; -4.366,-53.569 -4.366,-48.417 ; 11.432,-43.074 11.432,-37.91 ; 32.768,-43.074 32.768,-37.91 ; 64.95,-53.404 64.95,-37.91 ; 87.531,-53.404 127.549,-53.404 127.549,-37.91 -40.13,-37.91 -40.13,-53.404 25.834,-53.404 127.561,-53.404 127.561,-37.91
  text "COMPONENTS MARKED 'DNP' SHOULD NOT BE POPULATED." at 122.291,-32.677 h1.52
  text ".VariantName" at 95.773,-35.624 h1.52
  text "ASSEMBLY VARIANT:" at 122.164,-35.624 h1.52
  text ".VersionControl_RevNumber" at -6.398,-41.267 h1.52
  text "SVN REV:" at 6.454,-41.267 h1.52
  text ".PCB_Rev" at 20.335,-41.267 h1.52
  text "REV:" at 27.739,-41.267 h1.52
  text ".PRJ_Number" at 49.19,-41.267 h1.52
  text "BOARD #:" at 63.045,-41.267 h1.52
  text "PCB VIEWED FROM BOTTOM SIDE" at 125.948,-41.267 h1.52
  text ".TID" at 49.19,-46.431 h1.52
  text "TID #:" at 63.045,-46.431 h1.52
  text "TEXAS INSTRUMENTS" at -9.726,-51.647 h1.52
  text ".Print_Time" at 22.393,-51.647 h1.52
  text ".Print_Date" at 40.909,-51.647 h1.52
  text "GENERATED    :" at 62.994,-51.647 h1.52
  text ".plot_File_Name" at 105.489,-51.647 h1.52
  text "PLOT NAME =" at 125.948,-51.647 h1.52
M9 Title Sheet:
  drawing of 57 lines, arcs and shapes, not listed
  text "1" at -13.908,179.527 h1.78
  text "2" at 49.482,179.527 h1.78
  text "3" at 112.711,179.527 h1.78
  text "4" at 176.38,179.527 h1.78
  text "5" at 239.855,179.527 h1.78
  text "6" at 303.482,179.527 h1.78
  text "A" at -43.279,150.495 h1.78
  text "A" at 332.641,150.495 h1.78
  text "B" at -43.279,90.043 h1.78
  text "B" at 332.641,90.043 h1.78
  text "C" at -43.279,29.718 h1.78
  text "C" at 332.641,29.718 h1.78
  text "PROJECT TITLE:" at 255.425,-17.552 h1.14
  text ".PRJ_Title" at 256.695,-20.938 h1.78
  text "DESIGNED FOR:" at 255.425,-25.197 h1.14
  text ".PRJ_Customer" at 256.695,-28.753 h1.78
  text "D" at -43.279,-30.48 h1.78
  text "D" at 332.641,-30.48 h1.78
  text "FILE NAME:" at 255.425,-32.817 h1.14
  text ".PCB_File_Name_No_Path" at 256.695,-35.865 h1.78
  text "Texas Instruments (TI) and/or its licensors do not warrant the accuracy or completeness of this specification" at 129.2,-39.976 h1.14
  text "ENGINEER:" at 255.425,-40.183 h1.14
  text "LAYOUT BY:" at 293.652,-40.183 h1.14
  text "or any information contained therein. TI and/or its licensors do not warrant that this design will meet" at 128.057,-42.837 h1.14
  text ".PRJ_Engineer" at 256.695,-44.12 h1.78
  text ".PCB_Layout" at 294.935,-44.12 h1.78
  text "the specifications, will be suitable for your application or fit for any particular purpose, or will operate in" at 128.057,-45.699 h1.14
  text ".Layer_Name" at -18.044,-46.406 h1.52
  text "ALTIUM DESIGNER VERSION:" at 293.652,-48.057 h1.14
  text "an implementation. TI and/or its licensors do not warrant that the design is production worthy. You should" at 128.057,-48.561 h1.14
  text "completely validate and test your design implementation to confirm the system functionality for your application." at 129.2,-51.422 h1.14
  text ".print_Scale" at 256.695,-51.443 h1.78
  text ".Application_BuildNumber" at 294.935,-51.443 h1.78
  text "1" at -13.908,-56.693 h1.78
  text "2" at 49.482,-56.693 h1.78
  text "3" at 112.711,-56.693 h1.78
  text "4" at 176.38,-56.693 h1.78
  text "5" at 239.855,-56.693 h1.78
  text "6" at 303.482,-56.693 h1.78
M10 Fab Notes:
  drawing of 173 lines, arcs and shapes, not listed
  text "DESIGN INFORMATION" at 281.676,132.905 h1.52
  text "MIN. TRACK WIDTH:" at 265.304,128.333 h1.52
  text "8" at 293.149,128.333 h1.52
  text "MIL" at 297.08,128.333 h1.52
  text "MIN. CLEARANCE:" at 265.304,124.981 h1.52
  text "0.2" at 291.625,124.981 h1.52
  text "mm" at 297.08,124.981 h1.52
  text "MIN. VIA PAD SIZE:" at 265.304,121.628 h1.52
  text "24" at 292.387,121.628 h1.52
  text "MIL" at 297.08,121.628 h1.52
  text "0.05mm (2MIL)" at 282.957,118.028 h1.52
  text "MINIMUM ANNULAR RING" at 256.942,117.92 h1.52
  text "EXTERNAL" at 300.941,117.92 h1.52
  text "PER" at 262.022,114.922 h1.52
  text "IPC-D-275 CLASS 2 LEVEL C" at 267.61,114.922 h1.52
  text "MIL, HOLES" at 305.411,112.07 h1.52
  text "+/-" at 295.443,112.052 h1.52
  text "+/-" at 317.134,112.052 h1.52
  text "REGISTRATION TOLERANCES:" at 256.942,111.925 h1.52
  text "METAL" at 287.416,111.925 h1.52
  text "5" at 302.052,111.925 h1.52
  text "3" at 323.21,111.925 h1.52
  text "MIL" at 326.163,111.925 h1.52
  text "+/-" at 317.134,109.055 h1.52
  text "HOLE SIZE TOLERANCE (UNLESS OTHERWISE SPECIFIED):" at 256.942,108.928 h1.52
  text "3" at 323.21,108.928 h1.52
  text "MIL" at 326.163,108.928 h1.52
  text "MATERIAL:" at 255.043,103.608 h1.52
  text "FR-4 High Tg" at 280.099,100.043 h1.52
  text "FR-408" at 265.736,99.825 h1.52
  text "OTHER" at 303.531,99.825 h1.52
  text "X" at 276.164,99.733 h1.52
  text "62 MIL (1.6mm) +/-10%" at 273.867,95.692 h1.52
  text "THICKNESS:" at 256.942,95.584 h1.52
  text "X" at 270.611,95.584 h1.52
  text "OTHER" at 306.503,95.584 h1.52
  text "TOLERANCE:" at 256.942,91.57 h1.52
  text "X" at 278.26,91.57 h1.52
  text "ANSI IPC-6012 TYPE 3 CLASS 2" at 283.009,91.57 h1.52
  text "OTHER +/-" at 283.008,87.608 h1.52
  text "BOW & TWIST:" at 256.942,83.62 h1.52
  text "X" at 278.26,83.62 h1.52
  text "ANSI IPC-6012 TYPE 3 CLASS 2" at 283.009,83.62 h1.52
  text "OTHER +/-" at 283.008,79.594 h1.52
  text "DRILLING:" at 255.043,76.076 h1.52
  text "REFERENCE:" at 256.942,73.105 h1.52
  text "X" at 273.407,73.105 h1.52
  text "AS SHOWN" at 278.157,73.105 h1.52
  text "X" at 296.292,73.105 h1.52
  text "NC_DRILL FILES" at 299.772,73.105 h1.52
  text "PTH MIN COPPER THICKNESS:" at 256.942,69.091 h1.52
  text "X" at 291.238,69.091 h1.52
  text "1MIL" at 294.718,69.091 h1.52
  text "OTHER" at 307.341,69.091 h1.52
  text "BOARD FINISH:" at 255.043,65.053 h1.52
  text "SILKSCREEN:" at 258.985,62.056 h1.52
  text "X" at 283.084,62.056 h1.52
  text "TOP" at 286.285,62.056 h1.52
  text "X" at 296.038,62.056 h1.52
  text "BOTTOM" at 299.264,62.056 h1.52
  text "SILKSCREEN COLOR:" at 258.985,57.814 h1.52
  text "X" at 283.058,57.814 h1.52
  text "WHITE" at 286.285,57.814 h1.52
  text "OTHER" at 299.264,57.814 h1.52
  text "X" at 286.386,53.77 h1.52
  text "GREEN" at 289.612,53.77 h1.52
  text "OTHER" at 305.309,53.77 h1.52
  text "SOLDER RESIST COLOR:" at 258.985,53.496 h1.52
  text "X" at 286.386,49.452 h1.52
  text "MATTE" at 289.612,49.452 h1.52
  text "SEMI-GLOSS" at 305.298,49.436 h1.52
  text "IMMERSION GOLD (ENIG)" at 281.992,44.664 h1.52
  text "ENEPIG" at 315.966,44.58 h1.52
  text "SURFACE FINISH:" at 255.043,44.555 h1.52
  text "X" at 277.244,44.555 h1.52
  text "IMM. TIN/SILVER OR EQUIV" at 263.413,40.567 h1.52
  text "OTHER" at 299.772,40.567 h1.52
  text "ARRAY/PANEL:" at 255.043,36.021 h1.52
  text "CUT AND TRIM PER M1 BOARD OUTLINE" at 281.992,35.912 h1.52
  text "N.C. ROUTE" at 281.992,32.058 h1.52
  text "X" at 299.239,32.058 h1.52
  text "V. SCORE" at 303.989,32.058 h1.52
  text "CERTIFICATION:" at 255.043,28.578 h1.52
  text "MATERIALS AND WORKMANSHIP FOR ALL PCBS" at 273.458,28.578 h1.52
  text "TO MEET OR EXCEED THE REQUIREMENTS OF:" at 273.458,26.089 h1.52
  text "X" at 263.971,22.622 h1.52
  text "ANSI IPC-A-600F CLASS ->" at 267.502,22.622 h1.52
  text "X" at 309.134,22.622 h1.52
  text "2" at 312.155,22.622 h1.52
  text "1" at 304.154,22.584 h1.52
  text "3" at 321.146,22.584 h1.52
  text "X" at 284.648,18.571 h1.52
  text "RoHS" at 288.126,18.571 h1.52
  text "OTHER" at 304.494,18.571 h1.52
  text "PER ORDER" at 314.58,18.571 h1.52
  text "ALL BOARDS MUST MEET OR EXCEED UL94-V0 REQUIREMENTS." at 255.742,14.364 h1.52
  text "PCB MUST BEAR THE UL94V-0 UL REGISTERED MATERIAL ID NUMBER" at 255.742,11.316 h1.52
  text "ADDITIONAL REQUIREMENTS:" at 255.043,6.912 h1.52
  text "MICROSECTION:" at 256.942,3.991 h1.52
  text "YES" at 279.948,3.991 h1.52
  text "REQUIRED" at 301.83,0.025 h1.52
  text "BARE BOARD ELEC. TEST:" at 256.942,-0.047 h1.52
  text "NONE" at 290.108,-0.047 h1.52
  text "X" at 298.604,-0.047 h1.52
  text "PER ORDER" at 316.866,-0.047 h1.52
  text ".Layer_Name" at -18.044,-46.406 h1.52
M11 Gerber Information:
  lines w0.254: -40.117,-48.226 127.523,-48.226 ; -40.117,-43.062 127.574,-43.062 ; -40.117,-37.897 -40.117,-53.391 61.61,-53.391 127.574,-53.391 127.574,-37.897 -40.104,-37.897 -40.104,-53.391 -0.086,-53.391 ; 22.494,-53.391 22.494,-37.897 ; 54.676,-43.062 54.676,-37.897 ; 76.012,-43.062 76.012,-37.897 ; 91.811,-53.556 91.811,-48.404
  text "ALL ARTWORK VIEWED FROM TOP SIDE" at -38.504,-41.254 h1.52
  text "BOARD #:" at 24.399,-41.254 h1.52
  text ".PRJ_Number" at 38.255,-41.254 h1.52
  text "REV:" at 59.705,-41.254 h1.52
  text ".PCB_Rev" at 67.109,-41.254 h1.52
  text "SVN REV:" at 80.99,-41.254 h1.52
  text ".VersionControl_RevNumber" at 93.843,-41.254 h1.52
  text "LAYER NAME =" at -38.504,-46.406 h1.52
  text "TID #:" at 24.399,-46.419 h1.52
  text ".TID" at 38.255,-46.419 h1.52
  text "PLOT NAME =" at -38.504,-51.634 h1.52
  text ".plot_File_Name" at -18.044,-51.634 h1.52
  text "GENERATED    :" at 24.45,-51.634 h1.52
  text ".Print_Date" at 46.535,-51.634 h1.52
  text ".Print_Time" at 65.052,-51.634 h1.52
  text "TEXAS INSTRUMENTS" at 97.17,-51.634 h1.52
M12 Stackup:
  drawing of 191 lines, arcs and shapes, not listed
  text "Layer" at 215.981,174.282 h1.52
  text "Name" at 226.392,174.282 h1.52
  text "Material" at 250.008,174.282 h1.52
  text "Thickness" at 271.846,174.282 h1.52
  text "Constant" at 288.352,174.282 h1.52
  text "Board Layer Stack" at 302.826,174.282 h1.52
  text "1" at 215.981,171.234 h1.52
  text "Top Overlay" at 226.392,171.234 h1.52
  text "2" at 215.981,168.186 h1.52
  text "Top Solder" at 226.392,168.186 h1.52
  text "Solder Resist" at 250.008,168.186 h1.52
  text "0.40mil" at 271.846,168.186 h1.52
  text "3.5" at 288.352,168.186 h1.52
  text "3" at 215.981,165.138 h1.52
  text "Top Layer" at 226.392,165.138 h1.52
  text "Copper" at 250.008,165.138 h1.52
  text "1.40mil" at 271.846,165.138 h1.52
  text "4" at 215.981,162.09 h1.52
  text "Dielectric1" at 226.392,162.09 h1.52
  text "FR-4" at 250.008,162.09 h1.52
  text "59.20mil" at 271.846,162.09 h1.52
  text "4.8" at 288.352,162.09 h1.52
  text "5" at 215.981,159.042 h1.52
  text "Bottom Layer" at 226.392,159.042 h1.52
  text "Copper" at 250.008,159.042 h1.52
  text "1.40mil" at 271.846,159.042 h1.52
  text "6" at 215.981,155.994 h1.52
  text "Bottom Solder" at 226.392,155.994 h1.52
  text "Solder Resist" at 250.008,155.994 h1.52
  text "0.40mil" at 271.846,155.994 h1.52
  text "3.5" at 288.352,155.994 h1.52
  text "7" at 215.981,152.946 h1.52
  text "Bottom Overlay" at 226.392,152.946 h1.52
  text ".Layer_Name" at -18.044,-46.406 h1.52
M13 Component Bodies Top:
  text ".Layer_Name" at -18.044,-46.406 h1.52
M14 Component Bodies Bottom:
  text ".Layer_Name" at -18.044,-46.406 h1.52
M15 Courtyards Top:
  text ".Layer_Name" at -18.044,-46.406 h1.52
M16 Courtyards Bottom:
  text ".Layer_Name" at -18.044,-46.406 h1.52
Drill Drawing:
  circle w0.025: c108.847,34.458 r0.379
  circle w0.025: c108.847,34.458 r0.632
  lines w0.025: 108.215,30.033 108.215,30.349 108.531,30.665 108.215,30.981 108.215,31.298 108.531,31.298 108.847,30.981 109.163,31.298 109.479,31.298 109.479,30.981 109.163,30.665 109.479,30.349 109.479,30.033 109.163,30.033 108.847,30.349 108.531,30.033 108.215,30.033 ; 108.215,37.935 108.531,37.935 108.531,37.619 109.163,37.619 109.163,37.935 109.479,37.935 109.479,38.567 109.163,38.567 109.163,38.883 108.531,38.883 108.531,38.567 108.215,38.567 108.215,37.935 ; 108.215,41.411 108.847,41.728 109.479,41.411 109.163,42.044 109.479,42.676 108.847,42.36 108.215,42.676 108.531,42.044 108.215,41.411 ; 108.215,45.204 109.479,45.204 109.479,46.468 108.215,46.468 108.215,45.204 ; 108.215,50.261 109.479,50.261 108.847,48.997 108.215,50.261 ; 108.215,53.422 108.847,52.79 109.479,53.422 108.847,54.054 108.215,53.422 ; 108.215,56.898 108.531,56.898 108.847,56.582 109.163,56.898 109.479,56.898 109.163,57.214 109.479,57.531 109.163,57.531 108.847,57.847 108.531,57.531 108.215,57.531 108.531,57.214 108.215,56.898 ; 108.468,45.457 109.226,45.457 109.226,46.216 108.468,46.216 108.468,45.457 ; 108.468,57.025 108.657,57.025 108.847,56.835 109.037,57.025 109.226,57.025 109.037,57.214 109.226,57.404 109.037,57.404 108.847,57.594 108.657,57.404 108.468,57.404 108.657,57.214 108.468,57.025
  lines w0.305: 106.492,28.895 160.29,28.895 ; 106.492,59.237 160.29,59.237 ; 115.899,25.103 115.899,63.03 ; 124.967,25.103 124.967,63.03 ; 141.771,25.103 141.771,63.03 ; 148.988,25.103 148.988,63.03 ; 106.492,25.103 160.29,25.103 160.29,63.03 106.492,63.03 106.492,25.103
  text "Symbol" at 108.768,60.375 h1.83
  text "Quantity" at 117.037,60.375 h1.83
  text "Finished Hole Size" at 126.105,60.375 h1.83
  text "Plated" at 142.909,60.375 h1.83
  text "Hole Type" at 150.126,60.375 h1.83
  text "5" at 117.037,56.582 h1.52
  text "16.00mil (0.406mm)" at 126.105,56.582 h1.52
  text "PTH" at 142.909,56.582 h1.52
  text "Round" at 150.126,56.582 h1.52
  text "2" at 117.037,52.79 h1.52
  text "31.50mil (0.800mm)" at 126.105,52.79 h1.52
  text "PTH" at 142.909,52.79 h1.52
  text "Round" at 150.126,52.79 h1.52
  text "2" at 117.037,48.997 h1.52
  text "35.43mil (0.900mm)" at 126.105,48.997 h1.52
  text "PTH" at 142.909,48.997 h1.52
  text "Round" at 150.126,48.997 h1.52
  text "8" at 117.037,45.204 h1.52
  text "39.37mil (1.000mm)" at 126.105,45.204 h1.52
  text "PTH" at 142.909,45.204 h1.52
  text "Round" at 150.126,45.204 h1.52
  text "10" at 117.037,41.411 h1.52
  text "40.00mil (1.016mm)" at 126.105,41.411 h1.52
  text "PTH" at 142.909,41.411 h1.52
  text "Round" at 150.126,41.411 h1.52
  text "9" at 117.037,37.619 h1.52
  text "45.28mil (1.150mm)" at 126.105,37.619 h1.52
  text "PTH" at 142.909,37.619 h1.52
  text "Round" at 150.126,37.619 h1.52
  text "2" at 117.037,33.826 h1.52
  text "47.24mil (1.200mm)" at 126.105,33.826 h1.52
  text "PTH" at 142.909,33.826 h1.52
  text "Round" at 150.126,33.826 h1.52
  text "2" at 117.037,30.033 h1.52
  text "51.18mil (1.300mm)" at 126.105,30.033 h1.52
  text "PTH" at 142.909,30.033 h1.52
  text "Round" at 150.126,30.033 h1.52
  text "40 Total" at 117.037,26.241 h1.52
  text ".Layer_Name" at -18.044,-46.406 h1.52

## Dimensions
-32.7,-34.76 to -7.3,-34.76 on M2 Board Dimensions
-32.7,-24.6 to -32.7,63.03 on M2 Board Dimensions
-32.7,-24.6 to 93.03,-24.6 on M2 Board Dimensions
